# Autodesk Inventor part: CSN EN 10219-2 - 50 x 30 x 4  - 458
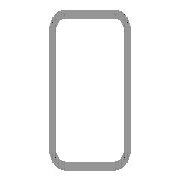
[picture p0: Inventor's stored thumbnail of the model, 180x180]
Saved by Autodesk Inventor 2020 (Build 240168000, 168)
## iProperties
Created: 2019-01
Part Number: CSN EN 10219-2 - 50 x 30 x 4  - 458
Material: Ocel, měkká
Description: Duté svařované profily tvářené za studena z nelegované a jemnozrnné konstrukční oceli
Document SubType Name: Modeling
Standard: CSN EN 10219-2
Designer: doma
Standards Organization: CSN
Language: cs-CZ
Size Designation: 50 x 30 x 4  - 458
Categories: <MemberInstance><Categories><Category DisplayName="Konstrukční profily" InternalName="089c4875-fa83-4c05-b084-43b9cc11f5ed" Mnemonic="GRDR"><CategoryParameter D
Stock Number: 50 x 30 x 4
Density: 7.85 g/cm^3
Appearance: Pololeštěná
IsCustomPart: 1
G_L: 458,000 mm
Author: doma
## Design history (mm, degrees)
node "Počáteční rovina"
node "Koncová rovina"
sketch "Náčrt"
  geometry: L1 (-15, -17)-(-15, 17); L2 (-7, 25)-(7, 25); L3 (15, 17)-(15, -17); L4 (7, -25)-(-7, -25); L5 (-7, 21)-(7, 21); L6 (11, 17)-(11, -17); L7 (7, -21)-(-7, -21); L8 (-11, -17)-(-11, 17); L9 (0, 37.102)-(0, -37.102) reference; L10 (-23.102, 0)-(23.102, 0) reference; A1 r 8 centre (-7, -17) between (-15, -17) and (-7, -25); A2 r 8 centre (-7, 17) between (-7, 25) and (-15, 17); A3 r 8 centre (7, 17) between (15, 17) and (7, 25); A4 r 8 centre (7, -17) between (7, -25) and (15, -17); A5 r 4 centre (-7, 17) between (-7, 21) and (-11, 17); A6 r 4 centre (7, 17) between (11, 17) and (7, 21); A7 r 4 centre (7, -17) between (7, -21) and (11, -17); A8 r 4 centre (-7, -17) between (-11, -17) and (-7, -21)
  constraints: 16 end point, 16 point on circle, 8 centre point, 8 tangent, 4 parallel, 3 equal radius, 2 perpendicular, 7 other
  dimensions: "d7" = 8 radius of A1 (= G_IR); "d10" = 50 distance between parallel lines of L2 L4 (= G_H); "d11" = 30 distance between parallel lines of L1 L3 (= G_W); "d12" = 4 distance between parallel lines of L3 L6 (= G_T); "d15" = 25 distance between parallel lines of L2 L10 (= 0.5 x d10); "d16" = 15 distance between parallel lines of L9 L3 (= 0.5 x d11)
extrude "Těleso" new body sketch "Náčrt" stored distance "d3" = 458 (= G_L); taper "d4" = 0 deg
node "Driven Length"
  sketch "Sketch3"
    geometry: L1 (0, 0)-(10, 0) reference
    constraints: 2 end point, 1 horizontal
  workplane "Work Plane3"
  sketch "Sketch4"
    geometry: L1 (-2, 0)-(12, 0) reference; L2 (-2, 458)-(12, 458) reference
    dimensions: "d18" = 458 distance between parallel lines of L1 L2 (derived)
body "Solid1"
other parameters: "G_W" = 30 [user parameter; used in 1 equation term], "G_H" = 50 [user parameter; used in 1 equation term], "G_T" = 4 [user parameter; used in 1 equation term], "G_IR" = 8 [user parameter; used in 1 equation term], "G_L" = 458 (= d18) [user parameter; used in 1 equation term], "G_OFFSET_START" = 0 [user parameter; used in 1 equation term], "G_OFFSET_END" = 0 [user parameter; used in 1 equation term], "d13" = 0 (computed from G_OFFSET_START), "d14" = 458 (= G_OFFSET_END + B_L), "B_L" = 458 [user parameter; used in 1 equation term], "d17" = 90 deg
